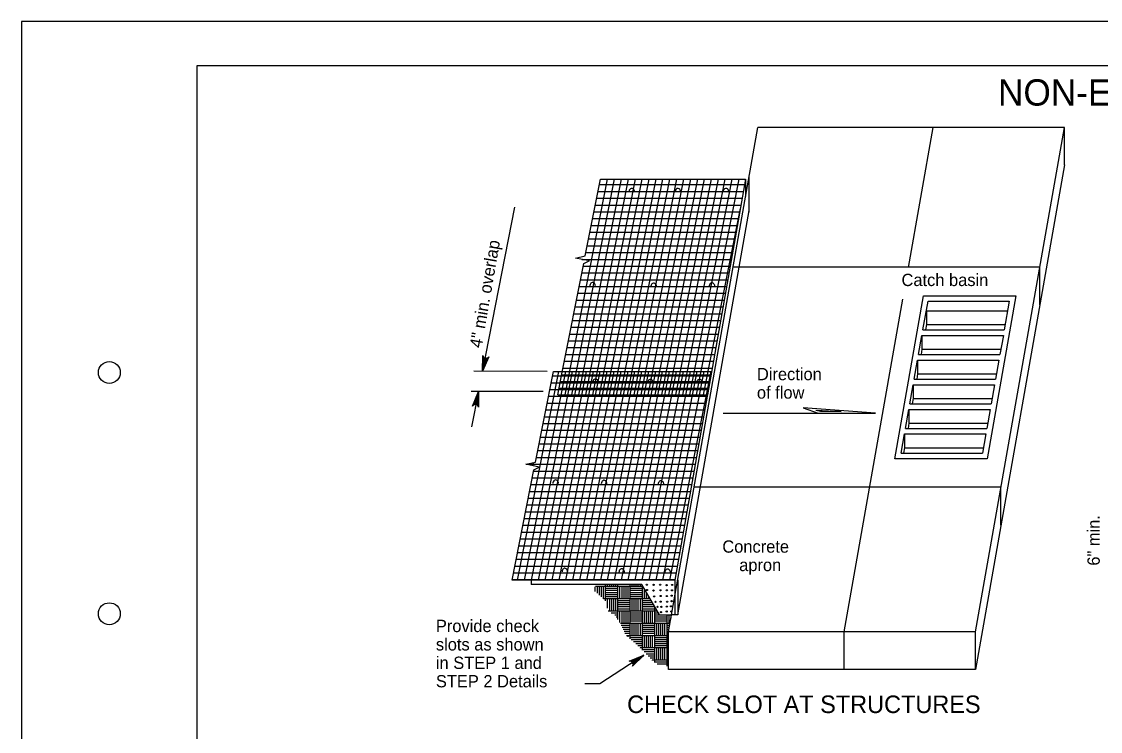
# Model space of a CAD drawing. Extents: x 1083.1 to 1117.1, y 719.4 to 741.4.
# Drawn here: x 1083.13 to 1095.42, y 733.26 to 741.35 of the extents above; entities that cross this region are included whole.
import ezdxf

# ---------------------------------------------------------------- set-up
doc = ezdxf.new("R2010")
doc.units = 0
for name, color, linetype in [('SH_Border', 7, 'Continuous'), ('SH_Cut_Line', 7, 'Continuous'), ('ST_Details', 7, 'Continuous'), ('ST_Text', 7, 'Continuous')]:
    doc.layers.add(name, color=color, linetype=linetype)

msp = doc.modelspace()

# ---------------------------------------------------------------- linework, layer by layer
at = {"layer": 'SH_Border'}
msp.add_lwpolyline([(1085.126, 740.854), (1116.626, 740.854), (1116.626, 719.854), (1085.126, 719.854)], close=True, dxfattribs=at)
for centre in [(1084.126, 737.354), (1084.126, 734.604)]:
    msp.add_circle(centre, 0.125, dxfattribs=at)
at = {"layer": 'SH_Cut_Line'}
msp.add_lwpolyline([(1083.126, 719.354), (1117.126, 719.354), (1117.126, 741.354), (1083.126, 741.354)], close=True, dxfattribs=at)
at = {"layer": 'ST_Details'}
for p, q in [((1090.497, 734.396), (1091.512, 740.148)), ((1095.007, 740.148), (1091.512, 740.148)), ((1093.228, 738.551), (1093.51, 740.148)), ((1093.993, 734.396), (1095.007, 740.148)), ((1095.007, 739.721), (1095.007, 740.148)), ((1095.007, 739.721), (1093.993, 733.969)), ((1091.411, 739.577), (1091.411, 739.181)), ((1089.317, 737.1), (1089.802, 739.556)), ((1089.396, 737.1), (1089.881, 739.556)), ((1089.475, 737.1), (1089.96, 739.556)), ((1089.548, 738.682), (1089.721, 739.556)), ((1089.554, 737.1), (1090.039, 739.556)), ((1089.633, 737.1), (1090.118, 739.556)), ((1089.709, 739.495), (1091.362, 739.495)), ((1089.711, 737.1), (1090.197, 739.556)), ((1089.721, 739.556), (1091.373, 739.556)), ((1089.79, 737.1), (1090.276, 739.556)), ((1089.869, 737.1), (1090.354, 739.556)), ((1089.948, 737.1), (1090.433, 739.556)), ((1090.027, 737.1), (1090.512, 739.556)), ((1090.106, 737.1), (1090.591, 739.556)), ((1090.185, 737.1), (1090.67, 739.556)), ((1090.264, 737.1), (1090.749, 739.556)), ((1090.342, 737.1), (1090.828, 739.556)), ((1090.421, 737.1), (1090.907, 739.556)), ((1090.5, 737.1), (1090.986, 739.556)), ((1090.579, 737.1), (1091.064, 739.556)), ((1090.658, 737.1), (1091.143, 739.556)), ((1090.737, 737.1), (1091.222, 739.556)), ((1090.816, 737.1), (1091.301, 739.556)), ((1091.373, 739.556), (1090.94, 737.1)), ((1091.373, 739.556), (1091.373, 739.361)), ((1089.678, 739.34), (1091.335, 739.34)), ((1089.694, 739.417), (1091.348, 739.417)), ((1088.379, 737.376), (1088.747, 739.238)), ((1089.663, 739.262), (1091.321, 739.262)), ((1090.895, 737.1), (1091.314, 739.224)), ((1089.632, 739.108), (1091.294, 739.108)), ((1089.648, 739.185), (1091.308, 739.185)), ((1090.601, 734.59), (1091.415, 739.202)), ((1089.617, 739.03), (1091.28, 739.03)), ((1089.587, 738.876), (1091.253, 738.876)), ((1089.602, 738.953), (1091.267, 738.953)), ((1089.556, 738.721), (1091.226, 738.721)), ((1089.571, 738.798), (1091.239, 738.798)), ((1089.286, 737.357), (1089.531, 738.595)), ((1089.438, 738.659), (1089.548, 738.682)), ((1089.595, 738.625), (1089.438, 738.659)), ((1089.51, 738.643), (1091.212, 738.643)), ((1089.531, 738.595), (1089.592, 738.625)), ((1089.51, 738.489), (1091.185, 738.489)), ((1089.525, 738.566), (1091.198, 738.566)), ((1094.726, 738.556), (1091.231, 738.556)), ((1094.726, 738.126), (1094.726, 738.553)), ((1089.495, 738.411), (1091.171, 738.411)), ((1089.464, 738.257), (1091.144, 738.257)), ((1089.479, 738.334), (1091.157, 738.334)), ((1093.073, 736.371), (1093.401, 738.229)), ((1093.401, 738.229), (1094.452, 738.229)), ((1094.452, 738.229), (1094.124, 736.371)), ((1089.434, 738.102), (1091.117, 738.102)), ((1089.449, 738.179), (1091.13, 738.179)), ((1092.495, 734.396), (1093.164, 738.188)), ((1093.394, 737.839), (1093.452, 738.167)), ((1093.452, 738.167), (1094.378, 738.167)), ((1094.378, 738.167), (1094.321, 737.839)), ((1089.418, 738.024), (1091.103, 738.024)), ((1093.433, 738.058), (1094.359, 738.058)), ((1093.433, 738.058), (1093.433, 737.902)), ((1089.388, 737.87), (1091.076, 737.87)), ((1089.403, 737.947), (1091.089, 737.947)), ((1093.433, 737.902), (1093.422, 737.839)), ((1093.433, 737.902), (1094.332, 737.902)), ((1089.372, 737.792), (1091.062, 737.792)), ((1093.345, 737.558), (1093.383, 737.777)), ((1093.383, 737.777), (1094.31, 737.777)), ((1093.383, 737.777), (1093.383, 737.621)), ((1093.394, 737.839), (1094.321, 737.839)), ((1094.31, 737.777), (1094.271, 737.558)), ((1089.342, 737.638), (1091.035, 737.638)), ((1089.357, 737.715), (1091.048, 737.715)), ((1093.383, 737.621), (1093.372, 737.558)), ((1093.383, 737.621), (1094.282, 737.621)), ((1088.389, 737.53), (1088.377, 737.368)), ((1088.435, 737.522), (1088.377, 737.368)), ((1088.398, 737.522), (1088.377, 737.368)), ((1088.409, 737.518), (1088.377, 737.368)), ((1088.424, 737.518), (1088.377, 737.368)), ((1089.327, 737.56), (1091.021, 737.56)), ((1093.295, 737.277), (1093.334, 737.496)), ((1093.334, 737.496), (1094.26, 737.496)), ((1093.334, 737.496), (1093.334, 737.34)), ((1093.345, 737.558), (1094.271, 737.558)), ((1094.26, 737.496), (1094.221, 737.277)), ((1089.114, 737.364), (1088.278, 737.369)), ((1089.296, 737.405), (1090.994, 737.405)), ((1089.311, 737.483), (1091.007, 737.483)), ((1088.776, 734.986), (1089.246, 737.364)), ((1088.855, 734.986), (1089.325, 737.364)), ((1088.934, 734.986), (1089.404, 737.364)), ((1088.98, 736.331), (1089.184, 737.364)), ((1089.013, 734.986), (1089.483, 737.364)), ((1089.091, 734.986), (1089.561, 737.364)), ((1089.17, 734.986), (1089.64, 737.364)), ((1089.174, 737.315), (1090.978, 737.315)), ((1089.184, 737.364), (1090.986, 737.364)), ((1089.236, 737.1), (1089.286, 737.357)), ((1089.249, 734.986), (1089.719, 737.364)), ((1089.266, 737.252), (1090.965, 737.252)), ((1089.281, 737.328), (1090.98, 737.328)), ((1089.328, 734.986), (1089.798, 737.364)), ((1089.407, 734.986), (1089.877, 737.364)), ((1089.486, 734.986), (1089.956, 737.364)), ((1089.565, 734.986), (1090.035, 737.364)), ((1089.644, 734.986), (1090.114, 737.364)), ((1089.723, 734.986), (1090.192, 737.364)), ((1089.801, 734.986), (1090.271, 737.364)), ((1089.88, 734.986), (1090.35, 737.364)), ((1089.959, 734.986), (1090.429, 737.364)), ((1090.038, 734.986), (1090.508, 737.364)), ((1090.117, 734.986), (1090.587, 737.364)), ((1090.196, 734.986), (1090.666, 737.364)), ((1090.275, 734.986), (1090.745, 737.364)), ((1090.354, 734.986), (1090.824, 737.364)), ((1090.432, 734.986), (1090.902, 737.364)), ((1090.511, 734.986), (1090.981, 737.364)), ((1090.986, 737.364), (1090.567, 734.986)), ((1093.295, 737.277), (1094.221, 737.277)), ((1093.334, 737.34), (1093.323, 737.277)), ((1093.334, 737.34), (1094.232, 737.34)), ((1089.067, 737.138), (1088.248, 737.138)), ((1088.332, 737.138), (1088.252, 736.733)), ((1088.276, 736.984), (1088.332, 737.138)), ((1088.287, 736.988), (1088.332, 737.138)), ((1088.302, 736.988), (1088.332, 737.138)), ((1088.313, 736.984), (1088.332, 737.138)), ((1088.323, 736.976), (1088.332, 737.138)), ((1089.144, 737.16), (1090.95, 737.16)), ((1089.159, 737.237), (1090.964, 737.237)), ((1089.251, 737.176), (1090.95, 737.176)), ((1093.246, 736.996), (1093.284, 737.215)), ((1093.284, 737.215), (1094.21, 737.215)), ((1093.284, 737.215), (1093.284, 737.059)), ((1094.21, 737.215), (1094.172, 736.996)), ((1089.113, 737.005), (1090.923, 737.005)), ((1089.128, 737.083), (1090.937, 737.083)), ((1089.236, 737.1), (1090.94, 737.1)), ((1093.246, 736.996), (1094.172, 736.996)), ((1093.284, 737.059), (1093.273, 736.996)), ((1093.284, 737.059), (1094.183, 737.059)), ((1089.098, 736.928), (1090.909, 736.928)), ((1091.118, 736.889), (1092.854, 736.889)), ((1092.854, 736.889), (1092.03, 736.952)), ((1092.03, 736.952), (1092.201, 736.892)), ((1092.174, 736.926), (1092.462, 736.91)), ((1092.229, 736.91), (1092.179, 736.921)), ((1092.462, 736.91), (1092.229, 736.91)), ((1093.196, 736.715), (1093.235, 736.934)), ((1093.235, 736.934), (1094.161, 736.934)), ((1093.235, 736.934), (1093.235, 736.777)), ((1094.161, 736.934), (1094.122, 736.715)), ((1089.067, 736.773), (1090.882, 736.773)), ((1089.083, 736.85), (1090.896, 736.85)), ((1093.235, 736.777), (1093.224, 736.715)), ((1093.235, 736.777), (1094.133, 736.777)), ((1089.052, 736.696), (1090.869, 736.696)), ((1093.146, 736.434), (1093.185, 736.653)), ((1093.185, 736.653), (1094.111, 736.653)), ((1093.185, 736.653), (1093.185, 736.496)), ((1093.196, 736.715), (1094.122, 736.715)), ((1094.111, 736.653), (1094.073, 736.434)), ((1089.021, 736.541), (1090.841, 736.541)), ((1089.037, 736.618), (1090.855, 736.618)), ((1088.991, 736.386), (1090.814, 736.386)), ((1089.006, 736.464), (1090.828, 736.464)), ((1093.146, 736.434), (1094.073, 736.434)), ((1093.185, 736.496), (1093.174, 736.434)), ((1093.185, 736.496), (1094.084, 736.496)), ((1088.87, 736.308), (1088.98, 736.331)), ((1089.024, 736.274), (1088.87, 736.308)), ((1088.873, 736.309), (1090.8, 736.309)), ((1088.879, 736.306), (1088.88, 736.31)), ((1088.955, 736.29), (1088.962, 736.327)), ((1088.963, 736.244), (1089.024, 736.274)), ((1094.124, 736.371), (1093.073, 736.371)), ((1088.714, 734.986), (1088.963, 736.244)), ((1088.945, 736.154), (1090.773, 736.154)), ((1088.96, 736.231), (1090.787, 736.231)), ((1088.93, 736.077), (1090.759, 736.077)), ((1094.284, 736.046), (1090.788, 736.046)), ((1094.283, 735.614), (1094.283, 736.041)), ((1088.899, 735.922), (1090.732, 735.922)), ((1088.914, 735.999), (1090.746, 735.999)), ((1088.869, 735.767), (1090.705, 735.767)), ((1088.884, 735.845), (1090.718, 735.845)), ((1088.853, 735.69), (1090.691, 735.69)), ((1088.823, 735.535), (1090.664, 735.535)), ((1088.838, 735.612), (1090.678, 735.612)), ((1088.807, 735.458), (1090.65, 735.458)), ((1088.777, 735.303), (1090.623, 735.303)), ((1088.792, 735.38), (1090.637, 735.38)), ((1088.761, 735.226), (1090.609, 735.226)), ((1088.731, 735.071), (1090.582, 735.071)), ((1088.746, 735.148), (1090.596, 735.148)), ((1090.567, 734.986), (1088.714, 734.986)), ((1088.715, 734.993), (1090.568, 734.993)), ((1088.93, 734.986), (1088.93, 734.939)), ((1090.192, 734.939), (1088.93, 734.939)), ((1089.662, 734.858), (1089.662, 734.909)), ((1090.207, 734.914), (1089.663, 734.914)), ((1089.779, 734.937), (1089.665, 734.937)), ((1089.686, 734.844), (1089.686, 734.914)), ((1089.709, 734.844), (1089.709, 734.914)), ((1089.732, 734.844), (1089.732, 734.914)), ((1089.756, 734.844), (1089.756, 734.914)), ((1089.779, 734.753), (1089.779, 734.939)), ((1089.802, 734.914), (1089.802, 734.939)), ((1089.826, 734.914), (1089.826, 734.939)), ((1089.849, 734.914), (1089.849, 734.939)), ((1089.872, 734.914), (1089.872, 734.939)), ((1089.896, 734.914), (1089.896, 734.939)), ((1089.919, 734.537), (1089.919, 734.939)), ((1090.059, 734.937), (1089.919, 734.937)), ((1089.942, 734.844), (1089.942, 734.914)), ((1089.966, 734.844), (1089.966, 734.914)), ((1089.989, 734.844), (1089.989, 734.914)), ((1090.012, 734.844), (1090.012, 734.914)), ((1090.036, 734.844), (1090.036, 734.914)), ((1090.059, 734.318), (1090.059, 734.939)), ((1090.082, 734.914), (1090.082, 734.939)), ((1090.106, 734.914), (1090.106, 734.939)), ((1090.129, 734.914), (1090.129, 734.939)), ((1090.152, 734.914), (1090.152, 734.939)), ((1090.175, 734.914), (1090.175, 734.939)), ((1090.394, 734.59), (1090.192, 734.939)), ((1090.199, 734.187), (1090.199, 734.928)), ((1090.567, 734.986), (1090.567, 734.792)), ((1090.601, 734.986), (1090.601, 734.59)), ((1089.686, 734.837), (1089.686, 734.844)), ((1089.709, 734.816), (1089.709, 734.844)), ((1089.732, 734.795), (1089.732, 734.844)), ((1089.756, 734.774), (1089.756, 734.844)), ((1089.849, 734.891), (1089.779, 734.891)), ((1089.849, 734.868), (1089.779, 734.868)), ((1089.849, 734.844), (1089.779, 734.844)), ((1089.849, 734.821), (1089.779, 734.821)), ((1089.849, 734.798), (1089.779, 734.798)), ((1089.919, 734.891), (1089.849, 734.891)), ((1089.919, 734.868), (1089.849, 734.868)), ((1089.919, 734.844), (1089.849, 734.844)), ((1089.919, 734.821), (1089.849, 734.821)), ((1089.919, 734.798), (1089.849, 734.798)), ((1089.942, 734.774), (1089.942, 734.844)), ((1089.966, 734.774), (1089.966, 734.844)), ((1089.989, 734.774), (1089.989, 734.844)), ((1090.012, 734.774), (1090.012, 734.844)), ((1090.036, 734.774), (1090.036, 734.844)), ((1090.129, 734.891), (1090.059, 734.891)), ((1090.129, 734.868), (1090.059, 734.868)), ((1090.129, 734.844), (1090.059, 734.844)), ((1090.129, 734.821), (1090.059, 734.821)), ((1090.129, 734.798), (1090.059, 734.798)), ((1090.199, 734.891), (1090.129, 734.891)), ((1090.199, 734.868), (1090.129, 734.868)), ((1090.199, 734.844), (1090.129, 734.844)), ((1090.199, 734.821), (1090.129, 734.821)), ((1090.199, 734.798), (1090.129, 734.798)), ((1090.222, 734.844), (1090.222, 734.888)), ((1090.222, 734.774), (1090.222, 734.844)), ((1090.245, 734.774), (1090.245, 734.847)), ((1090.245, 734.844), (1090.245, 734.847)), ((1090.269, 734.774), (1090.269, 734.807)), ((1090.567, 734.792), (1090.567, 734.59)), ((1090.288, 734.774), (1089.756, 734.774)), ((1089.802, 734.669), (1089.802, 734.774)), ((1089.826, 734.634), (1089.826, 734.774)), ((1089.849, 734.634), (1089.849, 734.774)), ((1089.872, 734.634), (1089.872, 734.774)), ((1089.896, 734.634), (1089.896, 734.774)), ((1090.059, 734.751), (1089.919, 734.751)), ((1090.059, 734.728), (1089.919, 734.728)), ((1090.059, 734.704), (1089.919, 734.704)), ((1090.059, 734.681), (1089.919, 734.681)), ((1090.082, 734.634), (1090.082, 734.774)), ((1090.106, 734.634), (1090.106, 734.774)), ((1090.129, 734.634), (1090.129, 734.774)), ((1090.152, 734.634), (1090.152, 734.774)), ((1090.175, 734.634), (1090.175, 734.774)), ((1090.301, 734.751), (1090.199, 734.751)), ((1090.315, 734.728), (1090.199, 734.728)), ((1090.328, 734.704), (1090.199, 734.704)), ((1090.339, 734.681), (1090.199, 734.681)), ((1090.339, 734.048), (1090.339, 734.686)), ((1090.369, 734.634), (1089.81, 734.634)), ((1089.849, 734.611), (1089.842, 734.611)), ((1089.919, 734.611), (1089.849, 734.611)), ((1089.919, 734.588), (1089.884, 734.588)), ((1089.919, 734.564), (1089.9, 734.564)), ((1089.919, 734.541), (1089.916, 734.541)), ((1090.059, 734.658), (1089.919, 734.658)), ((1089.942, 734.564), (1089.942, 734.634)), ((1089.942, 734.503), (1089.942, 734.564)), ((1089.966, 734.564), (1089.966, 734.634)), ((1089.966, 734.494), (1089.966, 734.564)), ((1089.989, 734.564), (1089.989, 734.634)), ((1089.989, 734.494), (1089.989, 734.564)), ((1090.012, 734.564), (1090.012, 734.634)), ((1090.012, 734.494), (1090.012, 734.564)), ((1090.036, 734.564), (1090.036, 734.634)), ((1090.036, 734.494), (1090.036, 734.564)), ((1090.129, 734.611), (1090.059, 734.611)), ((1090.129, 734.588), (1090.059, 734.588)), ((1090.129, 734.564), (1090.059, 734.564)), ((1090.129, 734.541), (1090.059, 734.541)), ((1090.199, 734.611), (1090.129, 734.611)), ((1090.199, 734.588), (1090.129, 734.588)), ((1090.199, 734.564), (1090.129, 734.564)), ((1090.199, 734.541), (1090.129, 734.541)), ((1090.339, 734.658), (1090.199, 734.658)), ((1090.222, 734.564), (1090.222, 734.634)), ((1090.222, 734.494), (1090.222, 734.564)), ((1090.245, 734.564), (1090.245, 734.634)), ((1090.245, 734.494), (1090.245, 734.564)), ((1090.269, 734.564), (1090.269, 734.634)), ((1090.269, 734.494), (1090.269, 734.564)), ((1090.292, 734.564), (1090.292, 734.634)), ((1090.292, 734.494), (1090.292, 734.564)), ((1090.315, 734.564), (1090.315, 734.634)), ((1090.315, 734.494), (1090.315, 734.564)), ((1090.382, 734.611), (1090.339, 734.611)), ((1090.409, 734.588), (1090.339, 734.588)), ((1090.409, 734.564), (1090.339, 734.564)), ((1090.409, 734.541), (1090.339, 734.541)), ((1090.362, 734.634), (1090.362, 734.646)), ((1090.394, 734.59), (1090.532, 734.59)), ((1090.479, 734.588), (1090.409, 734.588)), ((1090.479, 734.564), (1090.409, 734.564)), ((1090.479, 734.541), (1090.409, 734.541)), ((1090.479, 734.005), (1090.479, 734.59)), ((1090.502, 734.564), (1090.502, 734.59)), ((1090.502, 734.494), (1090.502, 734.564)), ((1090.525, 734.555), (1090.525, 734.59)), ((1090.601, 734.59), (1090.532, 734.59)), ((1090.515, 734.494), (1089.948, 734.494)), ((1090.059, 734.471), (1089.958, 734.471)), ((1090.059, 734.448), (1089.969, 734.448)), ((1090.059, 734.424), (1089.979, 734.424)), ((1090.129, 734.518), (1090.059, 734.518)), ((1090.082, 734.354), (1090.082, 734.494)), ((1090.106, 734.354), (1090.106, 734.494)), ((1090.199, 734.518), (1090.129, 734.518)), ((1090.129, 734.354), (1090.129, 734.494)), ((1090.152, 734.354), (1090.152, 734.494)), ((1090.175, 734.354), (1090.175, 734.494)), ((1090.339, 734.471), (1090.199, 734.471)), ((1090.339, 734.448), (1090.199, 734.448)), ((1090.339, 734.424), (1090.199, 734.424)), ((1090.409, 734.518), (1090.339, 734.518)), ((1090.362, 734.354), (1090.362, 734.494)), ((1090.385, 734.354), (1090.385, 734.494)), ((1090.479, 734.518), (1090.409, 734.518)), ((1090.409, 734.354), (1090.409, 734.494)), ((1090.432, 734.354), (1090.432, 734.494)), ((1090.455, 734.354), (1090.455, 734.494)), ((1090.51, 734.471), (1090.479, 734.471)), ((1090.506, 734.448), (1090.479, 734.448)), ((1090.502, 734.424), (1090.479, 734.424)), ((1090.059, 734.401), (1089.989, 734.401)), ((1090.059, 734.378), (1090, 734.378)), ((1090.497, 734.354), (1090.019, 734.354)), ((1090.036, 734.34), (1090.036, 734.354)), ((1090.129, 734.331), (1090.059, 734.331)), ((1090.129, 734.308), (1090.07, 734.308)), ((1090.199, 734.331), (1090.129, 734.331)), ((1090.199, 734.308), (1090.129, 734.308)), ((1090.339, 734.401), (1090.199, 734.401)), ((1090.339, 734.378), (1090.199, 734.378)), ((1090.222, 734.285), (1090.222, 734.354)), ((1090.245, 734.285), (1090.245, 734.354)), ((1090.269, 734.285), (1090.269, 734.354)), ((1090.292, 734.285), (1090.292, 734.354)), ((1090.315, 734.285), (1090.315, 734.354)), ((1090.409, 734.331), (1090.339, 734.331)), ((1090.409, 734.308), (1090.339, 734.308)), ((1090.479, 734.331), (1090.409, 734.331)), ((1090.479, 734.308), (1090.409, 734.308)), ((1090.498, 734.401), (1090.479, 734.401)), ((1090.497, 734.378), (1090.479, 734.378)), ((1090.497, 733.969), (1090.497, 734.396)), ((1093.993, 734.396), (1090.497, 734.396)), ((1092.495, 733.969), (1092.495, 734.396)), ((1093.993, 733.969), (1093.993, 734.396)), ((1090.129, 734.285), (1090.096, 734.285)), ((1090.129, 734.261), (1090.122, 734.261)), ((1090.199, 734.285), (1090.129, 734.285)), ((1090.199, 734.261), (1090.129, 734.261)), ((1090.199, 734.238), (1090.147, 734.238)), ((1090.497, 734.215), (1090.172, 734.215)), ((1090.175, 734.211), (1090.175, 734.215)), ((1090.339, 734.191), (1090.199, 734.191)), ((1090.222, 734.215), (1090.222, 734.285)), ((1090.245, 734.215), (1090.245, 734.285)), ((1090.269, 734.215), (1090.269, 734.285)), ((1090.292, 734.215), (1090.292, 734.285)), ((1090.315, 734.215), (1090.315, 734.285)), ((1090.409, 734.285), (1090.339, 734.285)), ((1090.409, 734.261), (1090.339, 734.261)), ((1090.409, 734.238), (1090.339, 734.238)), ((1090.362, 734.075), (1090.362, 734.215)), ((1090.385, 734.075), (1090.385, 734.215)), ((1090.479, 734.285), (1090.409, 734.285)), ((1090.479, 734.261), (1090.409, 734.261)), ((1090.479, 734.238), (1090.409, 734.238)), ((1090.409, 734.075), (1090.409, 734.215)), ((1090.432, 734.075), (1090.432, 734.215)), ((1090.455, 734.075), (1090.455, 734.215)), ((1090.497, 734.191), (1090.479, 734.191)), ((1090.064, 734.063), (1090.213, 734.132)), ((1090.075, 734.058), (1090.213, 734.132)), ((1090.086, 734.048), (1090.213, 734.132)), ((1090.09, 734.037), (1090.213, 734.132)), ((1090.092, 734.025), (1090.213, 734.132)), ((1090.339, 734.168), (1090.218, 734.168)), ((1090.339, 734.145), (1090.241, 734.145)), ((1090.339, 734.121), (1090.265, 734.121)), ((1090.339, 734.098), (1090.288, 734.098)), ((1090.497, 734.075), (1090.311, 734.075)), ((1090.315, 734.071), (1090.315, 734.075)), ((1090.409, 734.051), (1090.339, 734.051)), ((1090.479, 734.051), (1090.409, 734.051)), ((1090.497, 734.168), (1090.479, 734.168)), ((1090.497, 734.145), (1090.479, 734.145)), ((1090.497, 734.121), (1090.479, 734.121)), ((1090.497, 734.098), (1090.479, 734.098)), ((1090.409, 734.028), (1090.365, 734.028)), ((1090.479, 734.028), (1090.409, 734.028)), ((1093.993, 733.969), (1090.497, 733.969))]:
    msp.add_line(p, q, dxfattribs=at)
for points in [[(1088.449, 737.534), (1088.377, 737.368), (1088.379, 737.549)], [(1088.263, 736.971), (1088.332, 737.138), (1088.332, 736.957)], [(1090.213, 734.132), (1089.714, 733.806), (1089.541, 733.806)], [(1090.046, 734.064), (1090.213, 734.132), (1090.085, 734.005)]]:
    msp.add_lwpolyline(points, dxfattribs=at)
for centre, start, end in [((1088.417, 737.555), 190.0563, 325.8824), ((1088.295, 736.95), 10.905, 146.7312), ((1090.054, 734.027), 325.5879, 101.4141)]:
    msp.add_arc(centre, 0.0382, start, end, dxfattribs=at)
for centre, major_axis, ratio, start_param, end_param in [((1090.604, 739.412), (-0.0049, 0.0407), 0.788117, 4.712337, 7.85393), ((1090.077, 739.411), (0.0007, 0.041), 0.78812, 4.712396, 7.853989), ((1091.15, 739.411), (0.0017, 0.0409), 0.788119, 4.712407, 7.854), ((1089.632, 738.339), (-0.0049, 0.0407), 0.788117, 4.712337, 7.85393), ((1090.328, 738.331), (-0.0049, 0.0407), 0.788117, 4.712337, 7.85393), ((1090.992, 738.335), (-0.0049, 0.0407), 0.788117, 4.712337, 7.85393), ((1089.664, 737.24), (0.0007, 0.041), 0.78812, 4.712396, 7.853989), ((1090.29, 737.236), (0.0007, 0.041), 0.78812, 4.712396, 7.853989), ((1090.847, 737.235), (0.0007, 0.041), 0.78812, 4.712396, 7.853989), ((1089.21, 736.088), (0.0007, 0.041), 0.78812, 4.712396, 7.853989), ((1089.762, 736.085), (0.0007, 0.041), 0.78812, 4.712396, 7.853989), ((1090.41, 736.078), (0.0007, 0.041), 0.78812, 4.712396, 7.853989), ((1089.315, 735.082), (0.0007, 0.041), 0.78812, 4.712396, 7.853989), ((1089.963, 735.075), (0.0007, 0.041), 0.78812, 4.712396, 7.853989), ((1090.486, 735.071), (0.0007, 0.041), 0.78812, 4.712396, 7.853989)]:
    msp.add_ellipse(centre, major_axis=major_axis, ratio=ratio, start_param=start_param, end_param=end_param, dxfattribs=at)
for centre in [(1090.249, 734.935), (1090.326, 734.934), (1090.4, 734.935), (1090.474, 734.929), (1090.537, 734.932), (1090.25, 734.874), (1090.324, 734.868), (1090.332, 734.802), (1090.405, 734.871), (1090.407, 734.806), (1090.476, 734.871), (1090.476, 734.806), (1090.531, 734.81), (1090.535, 734.871), (1090.348, 734.74), (1090.371, 734.682), (1090.406, 734.742), (1090.415, 734.683), (1090.476, 734.685), (1090.48, 734.741), (1090.525, 734.689), (1090.531, 734.747), (1090.41, 734.622), (1090.475, 734.629), (1090.528, 734.63)]:
    msp.add_ellipse(centre, major_axis=(0.00673, 0), ratio=0.999895, dxfattribs=at)

# ---------------------------------------------------------------- texts
at = {"layer": 'ST_Text'}
for s, height, p in [('NON-EXCELSIOR EROSION CONTROL MAT INSTALLATION', 0.3, (1094.249, 740.396)), ('Catch basin', 0.14, (1093.15, 738.339)), ('Direction', 0.14, (1091.503, 737.266)), ('of flow', 0.14, (1091.503, 737.056)), ('Concrete', 0.14, (1091.109, 735.3)), ('apron', 0.14, (1091.301, 735.09)), ('Provide check ', 0.14, (1087.846, 734.395)), ('slots as shown ', 0.14, (1087.846, 734.185)), ('in STEP 1 and', 0.14, (1087.846, 733.975)), ('STEP 2 Details', 0.14, (1087.846, 733.765)), ('CHECK SLOT AT STRUCTURES', 0.2, (1090.024, 733.472))]:
    msp.add_text(s, height=height, dxfattribs=at).set_placement(p)
for s, rotation, p in [('4" min. overlap', 80.1961, (1088.366, 737.627)), ('6" min.', 90, (1095.408, 735.152))]:
    msp.add_text(s, height=0.14, rotation=rotation, dxfattribs=at).set_placement(p)

doc.saveas('drawing.dxf')
